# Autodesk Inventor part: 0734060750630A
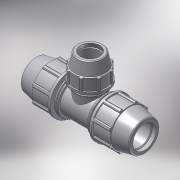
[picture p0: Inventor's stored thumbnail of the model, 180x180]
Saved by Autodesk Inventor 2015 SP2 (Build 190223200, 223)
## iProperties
Created: 2017-02
Part Number: 0734060750630A
Material: PVC-Piping
Description: PLASSON REDUCING TEE 75-63-75
Document SubType Name: Modeling
Designer: KIM
Mass: 92.6774 g
Surface Area: 199.44 cm^2
Volume: 66.1981 cm^3
Density: 1.4 g/cm^3
Appearance: Smooth - White
Author: KIM
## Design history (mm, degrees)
derived "87340.ipt"
feature "Solid1::87340.ipt"
feature "Solid2::87340.ipt"
tag "TaggingFeature1"
body "Solid1"
other parameters: "d2" = 75, "d4" = 14.70833, "d5" = 49.42, "d7" = 132, "d11" = 5.88333, "d13" = 120 deg, "d14" = 97.5, "d15" = 12 deg, "d16" = 114.84, "d18" = 3.75, "d19" = 35 deg, "d20" = 17.5 deg, "d21" = 122.76, "d23" = 0, "d25" = 360 deg, "d27" = 2.64, "d33" = 1.5, "d42" = 63.54, "d43" = 3.96, "d46" = 2.25, "d67" = 99, "d76" = 63, "d77" = 113, "d78" = 12 deg, "d79" = 153, "d80" = 120 deg, "d81" = 81.9, "d82" = 12.75, "d87" = 5.1, "d89" = 38.25, "d90" = 45.9, "d96" = 29.41667, "d98" = 105.09, "d99" = 35 deg, "d100" = 17.5 deg, "d102" = 0, "d103" = 2.26, "d107" = 360 deg, "d109" = 1.89, "d112" = 3.15, "d113" = 7.53333, "d114" = 0, "d117" = 353, "d118" = 98.31, "d126" = 67.5, "d127" = 132, "d131" = 7.65, "d132" = 56.7, "d133" = 109, "d135" = 0, "d138" = 10.59, "d143" = 0, "d148" = 84.75, "d168" = 67.5, "d170" = 0, "d171" = 63, "d173" = 0, "d176" = 7.53333, "d177" = 0, "d178" = 111.3948, "d179" = 3.53, "d180" = 3.53, "d181" = 2.55, "d182" = 95.3607, "d183" = 2.55, "d_" = 75, "E_" = 132, "A_" = 153, "l_" = 132, "E_1" = 113, "l_1" = 109, "d_1" = 63, "H_" = 353
